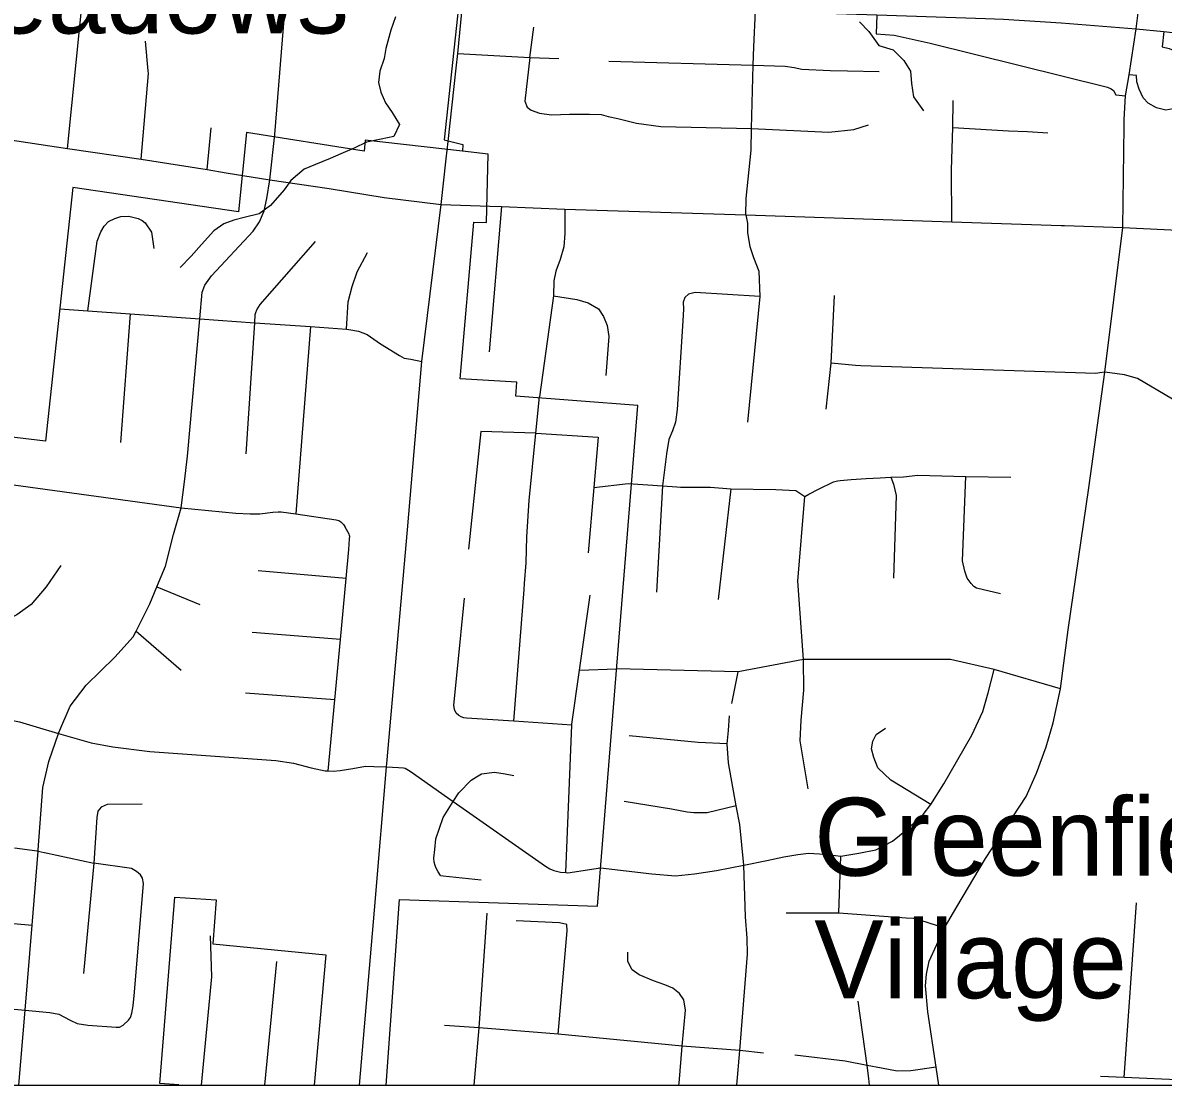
# Model space of a CAD drawing. Extents: x 0 to 69.5, y -4.5 to 22.
# Drawn here: x 6.973 to 8.129, y 14.2 to 15.277 of the extents above; entities that cross this region are included whole.
import ezdxf

# ---------------------------------------------------------------- set-up
doc = ezdxf.new("R2010")
doc.units = 0
for name, color, linetype in [('GM_X_City_Street', 7, 'Continuous'), ('GM_X_Corporation', 7, 'Continuous'), ('GM_X_County_Road', 7, 'Continuous'), ('GM_X_Interchange_Ramps', 7, 'Continuous'), ('GM_X_Minor_River', 7, 'Continuous'), ('GM_X_State_Route', 7, 'Continuous'), ('GM_X_Township_Subdivision', 7, 'Continuous'), ('GM_X_Unincorporated_Text', 7, 'Continuous'), ('SH_Data', 7, 'Continuous')]:
    doc.layers.add(name, color=color, linetype=linetype)

msp = doc.modelspace()

# ---------------------------------------------------------------- linework, layer by layer
at = {"layer": 'GM_X_City_Street'}
for points in [[(7.0179, 15.1499), (7.0394, 15.3649), (7.058, 15.5396)], [(7.2281, 15.1642), (7.2388, 15.2975), (7.2482, 15.3705)], [(7.0997, 15.2287), (7.0971, 15.2587)], [(7.0925, 15.1389), (7.0999, 15.226), (7.0997, 15.2287)], [(7.1594, 15.1284), (7.1637, 15.1708)], [(6.9082, 15.1664), (7.0179, 15.1499), (7.0925, 15.1389), (7.1594, 15.1284), (7.1788, 15.1253)], [(7.1332, 14.7855), (7.1364, 14.8117), (7.1396, 14.8378), (7.152, 14.9772), (7.1544, 15.0043), (7.1572, 15.0111), (7.1638, 15.0208), (7.2061, 15.0659), (7.2125, 15.0756), (7.2173, 15.0866), (7.2199, 15.0993), (7.2232, 15.1182), (7.2281, 15.1642)], [(7.3302, 14.3895), (7.3415, 14.5227), (7.3418, 14.5262), (7.3625, 14.7631), (7.3772, 14.9339), (7.3966, 15.093), (7.402, 15.1393), (7.4039, 15.1568)], [(7.1788, 15.1253), (7.2232, 15.1182), (7.2832, 15.1093), (7.3391, 15.1003), (7.3966, 15.093), (7.446, 15.0913)], [(7.0387, 14.9852), (7.0481, 15.056), (7.0518, 15.0652), (7.055, 15.0711), (7.0594, 15.0758), (7.066, 15.079), (7.072, 15.0808), (7.08, 15.0813), (7.0895, 15.0788), (7.0935, 15.0769), (7.0966, 15.0744), (7.1031, 15.0651), (7.1053, 15.0483)], [(7.1991, 14.8403), (7.2077, 14.9732), (7.2082, 14.9814), (7.2088, 14.9837), (7.21, 14.9864), (7.2131, 14.9915), (7.2693, 15.0556)], [(7.3009, 14.9666), (7.3025, 14.9942), (7.3067, 15.01), (7.3117, 15.0247), (7.3222, 15.0445)], [(7.01, 14.9872), (7.0387, 14.9852), (7.0813, 14.9822), (7.152, 14.9772), (7.2077, 14.9732), (7.2642, 14.9692), (7.3009, 14.9666), (7.3032, 14.9664), (7.313, 14.9646), (7.3217, 14.9613), (7.3351, 14.9518), (7.3545, 14.9398), (7.3593, 14.9374), (7.3661, 14.9361), (7.3772, 14.9339)], [(7.0813, 14.9822), (7.0717, 14.8518)], [(7.2642, 14.9692), (7.2494, 14.7793)], [(7.4808, 14.7027), (7.4812, 14.7089), (7.4828, 14.7298), (7.4837, 14.756), (7.486, 14.7928), (7.4927, 14.8613), (7.4964, 14.8981)], [(7.4927, 14.8613), (7.4369, 14.8629), (7.4246, 14.7435)], [(7.4927, 14.8613), (7.556, 14.857), (7.5515, 14.806), (7.5457, 14.7399)], [(6.7143, 14.8571), (6.7624, 14.8487), (6.8557, 14.8325), (6.8662, 14.828), (6.8819, 14.8207), (6.8932, 14.8181), (6.9099, 14.8161), (6.9533, 14.8102), (7.1332, 14.7855), (7.1886, 14.7802), (7.203, 14.7794), (7.2129, 14.7795), (7.2262, 14.781), (7.2315, 14.7815), (7.2346, 14.7815), (7.2494, 14.7793), (7.2903, 14.7734), (7.293, 14.7725), (7.295, 14.7713), (7.2976, 14.7687), (7.2995, 14.7659)], [(7.5515, 14.806), (7.5865, 14.81)], [(6.9993, 14.5292), (7.0087, 14.5568), (7.009, 14.5575), (7.0205, 14.5842), (7.0369, 14.6055), (7.066, 14.6342), (7.0846, 14.6547), (7.0875, 14.6604), (7.1013, 14.6882), (7.1084, 14.7052), (7.1172, 14.7262), (7.1255, 14.7583), (7.1332, 14.7855)], [(7.2823, 14.5188), (7.289, 14.5907), (7.2946, 14.652), (7.3003, 14.7138), (7.3031, 14.7433), (7.3039, 14.754), (7.304, 14.7563), (7.3039, 14.7574), (7.3035, 14.7589), (7.2995, 14.7659)], [(7.011, 14.7269), (6.9963, 14.7053), (6.981, 14.6875), (6.9666, 14.6769), (6.9522, 14.6694), (6.9304, 14.6597), (6.9248, 14.659), (6.9163, 14.6594), (6.9042, 14.662), (6.8953, 14.6676), (6.8855, 14.6792), (6.8605, 14.7093), (6.8266, 14.7502)], [(7.3003, 14.7138), (7.2112, 14.7217)], [(7.1084, 14.7052), (7.152, 14.6874)], [(7.4704, 14.569), (7.4808, 14.7027), (7.4808, 14.7027)], [(7.5231, 14.4157), (7.5292, 14.5651), (7.5293, 14.5662), (7.537, 14.6207), (7.5479, 14.6969)], [(7.4133, 14.6222), (7.4205, 14.6938)], [(7.0875, 14.6604), (7.133, 14.621)], [(7.2946, 14.652), (7.2052, 14.6592)], [(6.4722, 14.646), (6.6567, 14.621), (6.7251, 14.6117), (6.7895, 14.603), (6.7929, 14.6026), (6.9693, 14.5686), (6.9863, 14.5633), (7.0087, 14.5568), (7.0418, 14.5473), (7.0638, 14.5431), (7.1013, 14.5385), (7.2291, 14.5294), (7.2469, 14.5264), (7.2651, 14.5219), (7.2791, 14.5189), (7.2823, 14.5188), (7.2874, 14.5185), (7.2943, 14.519), (7.3072, 14.521), (7.3202, 14.5234), (7.3285, 14.5233), (7.3415, 14.5227)], [(7.5292, 14.5651), (7.4704, 14.569), (7.4223, 14.5722), (7.4198, 14.5726), (7.417, 14.5735), (7.4146, 14.5748), (7.4121, 14.5774), (7.4104, 14.581), (7.4096, 14.5854), (7.4133, 14.6222), (7.4133, 14.6222)], [(7.537, 14.6207), (7.5744, 14.6223)], [(7.289, 14.5907), (7.1984, 14.5975)], [(6.9685, 14.2), (6.9749, 14.2762), (6.982, 14.3624), (6.9882, 14.4373), (6.9883, 14.4386), (6.993, 14.502), (6.9989, 14.5281), (6.9992, 14.5291), (6.9993, 14.5292)], [(7.3415, 14.5227), (7.3536, 14.5222), (7.3586, 14.5219), (7.3604, 14.5214), (7.3653, 14.5183), (7.4091, 14.4876), (7.5024, 14.422), (7.507, 14.4194), (7.5111, 14.4177), (7.5179, 14.4161), (7.5231, 14.4157), (7.5251, 14.4155), (7.5584, 14.4204)], [(7.3962, 14.4128), (7.3937, 14.4163), (7.3915, 14.4206), (7.3908, 14.4227), (7.3897, 14.4263), (7.3895, 14.4303), (7.3903, 14.4391), (7.3913, 14.4498), (7.3989, 14.4716), (7.4091, 14.4876), (7.4146, 14.4964), (7.4271, 14.5094), (7.4325, 14.5128), (7.4378, 14.5157), (7.4508, 14.5173), (7.4618, 14.5159), (7.4705, 14.5139)], [(7.0936, 14.485), (7.0583, 14.4845), (7.0521, 14.4821), (7.0486, 14.478), (7.0476, 14.4716), (7.0447, 14.4253), (7.0342, 14.3131)], [(6.481, 14.4392), (6.7572, 14.3996), (6.8096, 14.3922), (6.8296, 14.3883), (6.8519, 14.3803), (6.8685, 14.3761), (6.895, 14.3699), (6.982, 14.3624)], [(6.9643, 14.4407), (6.9872, 14.4375), (6.9882, 14.4373), (6.9942, 14.436), (6.9946, 14.4359)], [(6.9946, 14.4359), (7.0447, 14.4253)], [(7.0857, 14.2945), (7.095, 14.4044), (7.0941, 14.4101), (7.0919, 14.4132), (7.0878, 14.4168), (7.0829, 14.4196), (7.0447, 14.4253)], [(7.3962, 14.4128), (7.3987, 14.4123), (7.4372, 14.4082)], [(6.9751, 14.2761), (7, 14.2738), (7.009, 14.272), (7.0206, 14.266), (7.0278, 14.2624), (7.0384, 14.2609), (7.0672, 14.2588), (7.0706, 14.2588), (7.0745, 14.261), (7.0799, 14.2658), (7.0818, 14.2687), (7.0832, 14.2729), (7.0845, 14.2805), (7.0857, 14.2943), (7.0857, 14.2945)], [(6.9154, 14.2816), (6.9749, 14.2762), (6.9751, 14.2761)]]:
    msp.add_lwpolyline(points, dxfattribs=at)
at = {"layer": 'GM_X_Corporation'}
for p, q in [((4.7755, 14.2), (7.1307, 14.2)), ((7.268, 14.2), (7.341, 14.2))]:
    msp.add_line(p, q, dxfattribs=at)
for points in [[(6.9605, 15.6641), (7.1222, 15.6381), (7.4375, 15.5883), (7.4066, 15.3204), (7.4172, 15.3188), (7.3999, 15.1585), (7.4188, 15.154), (7.4183, 15.1471), (7.3197, 15.1582), (7.3186, 15.147), (7.1994, 15.166), (7.1914, 15.0856), (7.0234, 15.1102), (6.9956, 14.8531), (6.7125, 14.887)], [(7.341, 14.2), (7.3546, 14.3882), (7.5553, 14.3815), (7.596, 14.8894), (7.4726, 14.8986), (7.4736, 14.913), (7.4159, 14.9164), (7.43, 15.0753), (7.4427, 15.0749), (7.4445, 15.1442), (7.4183, 15.1471), (7.3197, 15.1582), (7.3186, 15.147), (7.1994, 15.166), (7.1914, 15.0856), (7.0234, 15.1102), (6.9956, 14.8531), (6.7125, 14.887)], [(7.1307, 14.2), (7.1307, 14.2003), (7.1116, 14.2017), (7.1268, 14.3906), (7.1685, 14.3879), (7.1652, 14.3434), (7.2799, 14.3322), (7.268, 14.2)]]:
    msp.add_lwpolyline(points, dxfattribs=at)
at = {"layer": 'GM_X_County_Road'}
for points in [[(7.4119, 15.2314), (7.4135, 15.2462), (7.4204, 15.3166), (7.4241, 15.3465), (7.4291, 15.4031)], [(8.0892, 15.1724), (8.0893, 15.1794), (8.0906, 15.2033), (8.0943, 15.2247), (8.1014, 15.2712), (8.1035, 15.2873), (8.1057, 15.3008), (8.119, 15.3989), (8.1194, 15.402)], [(7.4039, 15.1568), (7.4119, 15.2314)], [(7.9014, 14.2), (7.8988, 14.2182), (7.8901, 14.2745), (7.8879, 14.3009), (7.8889, 14.3127), (7.8917, 14.3257), (7.907, 14.3595), (7.9195, 14.3809), (7.9486, 14.4299), (7.9899, 14.4927), (8.0002, 14.5165), (8.0101, 14.5432), (8.0173, 14.5674), (8.0246, 14.602), (8.0323, 14.6619), (8.0535, 14.8057), (8.0698, 14.9231), (8.088, 15.0696), (8.0892, 15.1724)], [(7.446, 15.0913), (7.4578, 15.0909), (7.5222, 15.0884), (7.7055, 15.0825), (7.9145, 15.0754), (8.0252, 15.0718), (8.0288, 15.0717)], [(8.0288, 15.0717), (8.088, 15.0696), (8.1646, 15.0661), (8.1707, 15.0658)], [(7.3141, 14.2), (7.3302, 14.3894), (7.3302, 14.3895)]]:
    msp.add_lwpolyline(points, dxfattribs=at)
at = {"layer": 'GM_X_Interchange_Ramps'}
for points in [[(7.8384, 15.2853), (7.8379, 15.2661), (7.8559, 15.2647), (7.8926, 15.2565), (8.0725, 15.212), (8.076, 15.2105), (8.0783, 15.2085), (8.0807, 15.2042), (8.0906, 15.2033)], [(8.1295, 15.2684), (8.1277, 15.253), (8.135, 15.2513), (8.1463, 15.2462), (8.1549, 15.2388), (8.1596, 15.2321), (8.1623, 15.2259), (8.1627, 15.2161), (8.1596, 15.2064), (8.1541, 15.1986), (8.1475, 15.1931), (8.1389, 15.19), (8.1315, 15.1888), (8.1221, 15.1911), (8.1135, 15.1958), (8.1085, 15.2013), (8.1046, 15.2099), (8.1022, 15.2173), (8.1017, 15.2238), (8.0943, 15.2247)]]:
    msp.add_lwpolyline(points, dxfattribs=at)
at = {"layer": 'GM_X_Minor_River'}
for points in [[(7.3503, 15.2834), (7.3458, 15.2698), (7.3408, 15.2513), (7.339, 15.2411), (7.3345, 15.2282), (7.3331, 15.2169), (7.3355, 15.2069), (7.3402, 15.1962), (7.3472, 15.1865), (7.3545, 15.1741)], [(7.821, 15.2784), (7.8303, 15.2686), (7.8406, 15.2543), (7.8549, 15.2498), (7.8657, 15.2392), (7.8726, 15.2284), (7.8735, 15.2158), (7.8758, 15.2021), (7.8857, 15.1882)], [(7.3545, 15.1741), (7.3489, 15.1621), (7.3359, 15.1594), (7.321, 15.1563), (7.3087, 15.1501), (7.2949, 15.1444), (7.2841, 15.1397), (7.2692, 15.1336), (7.258, 15.1289), (7.2444, 15.1175), (7.2377, 15.1078), (7.2237, 15.0921), (7.2121, 15.0837), (7.1972, 15.0799), (7.1865, 15.0771), (7.1765, 15.0735), (7.1664, 15.0665), (7.1539, 15.0524), (7.1434, 15.0405), (7.1321, 15.0293)]]:
    msp.add_lwpolyline(points, dxfattribs=at)
at = {"layer": 'GM_X_State_Route'}
msp.add_lwpolyline([(7.375, 15.3384), (7.3915, 15.3291), (7.4204, 15.3166), (7.4471, 15.3074), (7.4931, 15.2985), (7.5414, 15.2945), (7.7154, 15.2893), (7.8384, 15.2853), (7.9488, 15.2816), (7.9669, 15.2811), (8.0254, 15.2774), (8.1014, 15.2712), (8.1295, 15.2684), (8.2078, 15.2595), (8.2788, 15.2497), (8.3376, 15.2408), (8.412, 15.227), (8.4869, 15.2128), (8.558, 15.1957), (8.6387, 15.1753)], dxfattribs=at)
at = {"layer": 'GM_X_Township_Subdivision'}
for points in [[(7.7139, 15.2531), (7.7154, 15.2893), (7.7187, 15.3435)], [(7.4866, 15.2421), (7.4908, 15.273)], [(7.7055, 15.0825), (7.7061, 15.0993), (7.7112, 15.1483), (7.7114, 15.1702), (7.7131, 15.2344), (7.7139, 15.2531)], [(7.4135, 15.2462), (7.4866, 15.2421), (7.5159, 15.2412)], [(7.4866, 15.2421), (7.4817, 15.1979), (7.4839, 15.1918), (7.488, 15.1887), (7.4963, 15.1856), (7.5088, 15.1839), (7.527, 15.1845), (7.5472, 15.1848), (7.5589, 15.1842), (7.5662, 15.1824), (7.5758, 15.1803), (7.5949, 15.1754), (7.6195, 15.1721), (7.7114, 15.1702), (7.7897, 15.1665), (7.8152, 15.1692), (7.83, 15.174)], [(7.5667, 15.2384), (7.7131, 15.2344), (7.7456, 15.2333), (7.7547, 15.232), (7.7625, 15.2304), (7.7911, 15.229), (7.8088, 15.2286)], [(7.8088, 15.2286), (7.8408, 15.2279)], [(7.9145, 15.0754), (7.9142, 15.1281), (7.9154, 15.1712), (7.916, 15.1985)], [(7.9154, 15.1712), (7.9552, 15.1689), (7.9718, 15.1678), (7.9914, 15.1672), (8.0117, 15.1656)], [(7.4578, 15.0909), (7.4455, 14.9436)], [(7.5222, 15.0884), (7.5222, 15.0636), (7.5211, 15.05), (7.5175, 15.0373), (7.5129, 15.0253), (7.5109, 15.0156), (7.5108, 15.0004), (7.4964, 14.8981)], [(7.7055, 15.0825), (7.7074, 15.0741), (7.7075, 15.0643), (7.7097, 15.0506), (7.7133, 15.0394), (7.7187, 15.0253), (7.7199, 14.9998), (7.7074, 14.8722)], [(7.5108, 15.0004), (7.5343, 14.9966), (7.5459, 14.9934), (7.5564, 14.9871), (7.5615, 14.9795), (7.5651, 14.9704), (7.5668, 14.9592), (7.5638, 14.9195)], [(7.7199, 14.9998), (7.6542, 15.0038), (7.6475, 15.0021), (7.6439, 14.9989), (7.642, 14.9941), (7.6424, 14.9869), (7.6417, 14.9751), (7.6359, 14.8852), (7.6345, 14.8722), (7.6313, 14.8636), (7.6275, 14.8549), (7.6251, 14.8403), (7.6213, 14.8077), (7.6152, 14.6998)], [(7.787, 14.8856), (7.7921, 14.9323), (7.7956, 15.0009)], [(7.8223, 14.9296), (7.8167, 14.9298), (7.7921, 14.9323)], [(8.0647, 14.9224), (8.0606, 14.9218), (7.8223, 14.9296)], [(8.1382, 14.8955), (8.1029, 14.9166), (8.0895, 14.9202), (8.082, 14.9214), (8.0698, 14.9231), (8.0647, 14.9224)], [(7.6356, 14.8067), (7.6393, 14.8065), (7.67, 14.8065), (7.6906, 14.8048), (7.736, 14.8041), (7.7564, 14.8031), (7.7655, 14.7971), (7.7696, 14.7993), (7.7792, 14.8045), (7.7945, 14.8119), (7.7985, 14.813), (7.8014, 14.8132), (7.8123, 14.8143), (7.8276, 14.8151), (7.8417, 14.8158), (7.8528, 14.8167), (7.8656, 14.817), (7.8802, 14.8187), (7.9288, 14.8172), (7.9743, 14.8166)], [(7.8528, 14.8167), (7.8555, 14.8093), (7.8581, 14.7981), (7.8555, 14.7143)], [(7.9638, 14.6983), (7.9395, 14.7041), (7.9369, 14.7056), (7.9341, 14.7088), (7.9301, 14.7142), (7.9277, 14.7211), (7.9253, 14.7318), (7.9288, 14.8172)], [(7.5865, 14.81), (7.6213, 14.8077), (7.6356, 14.8067)], [(7.6906, 14.8048), (7.6776, 14.6925)], [(7.7688, 14.5006), (7.7609, 14.5492), (7.7616, 14.5702), (7.7643, 14.6006), (7.7641, 14.6318), (7.7583, 14.711), (7.7655, 14.7971)], [(8.0246, 14.602), (7.9575, 14.6214), (7.9132, 14.6317), (7.7641, 14.6318), (7.6978, 14.6193), (7.5744, 14.6223)], [(7.5584, 14.4204), (7.6102, 14.4144), (7.6345, 14.4124), (7.6536, 14.4142), (7.6758, 14.4178), (7.7036, 14.423), (7.7269, 14.4278), (7.7443, 14.4317), (7.7583, 14.434), (7.7691, 14.4352), (7.7857, 14.4342), (7.802, 14.4324), (7.8202, 14.4353), (7.8373, 14.4386), (7.8542, 14.4475), (7.8687, 14.459), (7.8853, 14.4746), (7.8933, 14.4848), (7.9063, 14.5055), (7.9349, 14.5551), (7.9459, 14.5791), (7.9515, 14.598), (7.9575, 14.6214)], [(7.6916, 14.5869), (7.6978, 14.6193)], [(7.6966, 14.2), (7.6996, 14.2353), (7.7072, 14.333), (7.707, 14.3491), (7.7052, 14.3708), (7.7036, 14.423), (7.6997, 14.4643), (7.6959, 14.4832), (7.6882, 14.5269), (7.6868, 14.5463), (7.688, 14.5598), (7.6892, 14.5747)], [(7.8933, 14.4848), (7.8526, 14.5093), (7.8396, 14.5219), (7.8355, 14.5323), (7.8332, 14.541), (7.8345, 14.5487), (7.8378, 14.5556), (7.8473, 14.562)], [(7.6868, 14.5463), (7.6572, 14.5476), (7.5875, 14.5543)], [(7.6959, 14.4832), (7.6666, 14.4761), (7.6528, 14.4761), (7.6461, 14.4769), (7.6304, 14.48), (7.5824, 14.4876)], [(7.8, 14.3749), (7.802, 14.4324)], [(8.0892, 14.2077), (8.1017, 14.385)], [(7.4301, 14.2), (7.4353, 14.2582), (7.4433, 14.3745)], [(7.7467, 14.3749), (7.8, 14.3749), (7.8681, 14.3696), (7.8757, 14.3694), (7.8828, 14.3672), (7.907, 14.3595)], [(7.5153, 14.2517), (7.5244, 14.3564), (7.5241, 14.3628), (7.5169, 14.3648), (7.4727, 14.3667)], [(7.1539, 14.2), (7.1644, 14.31), (7.163, 14.3513)], [(7.218, 14.2), (7.2303, 14.3256)], [(7.6376, 14.2), (7.6381, 14.202), (7.641, 14.2396), (7.6445, 14.2762), (7.6429, 14.2864), (7.6383, 14.293), (7.6317, 14.2985), (7.6234, 14.3018), (7.6122, 14.3059), (7.5975, 14.312), (7.5903, 14.317), (7.5861, 14.3253), (7.5861, 14.3348)], [(7.8311, 14.2), (7.8303, 14.2067), (7.8286, 14.2199), (7.8196, 14.2852)], [(7.7236, 14.2324), (7.6996, 14.2353), (7.641, 14.2396), (7.6029, 14.2434), (7.5153, 14.2517), (7.4353, 14.2582), (7.4003, 14.2604)], [(7.8988, 14.2182), (7.8728, 14.2145), (7.8591, 14.2141), (7.8431, 14.2174), (7.8286, 14.2199), (7.8065, 14.2244), (7.7555, 14.2306)], [(8.2622, 14.2), (8.2604, 14.2004), (8.2124, 14.2024), (8.1505, 14.2051), (8.0892, 14.2077), (8.0652, 14.2087)]]:
    msp.add_lwpolyline(points, dxfattribs=at)
at = {"layer": 'SH_Data'}
msp.add_line((2, 14.2), (8.8, 14.2), dxfattribs=at)

# ---------------------------------------------------------------- texts
at = {"layer": 'GM_X_Unincorporated_Text'}
for s, height, p in [('Spring Meadows', 0.078977, (6.5167, 15.2665)), ('Greenfield', 0.07898, (7.775, 14.4124)), ('Village', 0.07898, (7.775, 14.2882))]:
    msp.add_text(s, height=height, rotation=0, dxfattribs=at).set_placement(p)

doc.saveas('drawing.dxf')
